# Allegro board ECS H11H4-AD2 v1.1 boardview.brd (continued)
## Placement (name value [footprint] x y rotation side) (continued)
Q25  mmbt3904-s  [SOT23_BCE_2]  156.18 65.66 270 top
Q26  mmbt3904-s  [SOT23_BCE_2]  167.49 65.02 0 top
Q27  sm2305psa-s  [SOT23_GDS_2]  153.9 59.18 0 top
Q28  sm2300nsac-trg-s  [SOT23_GDS_2]  135.86 58.8 180 top
Q29  sm2305psa-s  [SOT23_GDS_2]  135.88 54.78 0 top
Q30  sm2305psa-s  [SOT23_GDS_2]  146.76 47.12 0 top
Q31  mmbt3904-s  [SOT23_BCE_2]  139.29 46.99 180 top
Q32  mmbt3904-s  [SOT23_BCE_2]  97.3 34.55 270 top
Q33  mmbt3904-s  [SOT23_BCE_2]  97.31 30.94 270 top
Q34  pmbs3906-s-o  [SOT23_BCE_2]  36.8 29.03 0 top
Q35  mmbt3904-s  [SOT23_BCE_2]  194.79 28.83 0 top
Q36  pmbs3906-s-o  [SOT23_BCE_2]  36.78 25.17 0 top
Q37  mmbt3904-s  [SOT23_BCE_2]  10.36 10.41 180 top
Q38  pmbs3906-s  [SOT23_BCE_2]  26.39 10.29 270 top
Q39  mmbt3904-s  [SOT23_BCE_2]  5.28 10.03 270 top
Q40  mmbt3904-s  [SOT23_BCE_2]  5.2 5.23 270 top
Q44  pmbs3906-s  [SOT23_BCE_2]  158.98 220.47 90 top
QBH1  sm4377nskpc-trg-s  [Q_TDSON8-GDS-4]  116.05 59.18 0 top
QBL1  sm4364nakpc-trg-s  [Q_TDSON8-GDS-4]  116.05 51.56 0 top
QCGH1  sm4377nskpc-trg-s  [Q_TDSON8-GDS-4]  189.71 153.03 270 top
QCGH2  sm4377nskpc-trg-s  [Q_TDSON8-GDS-4]  189.71 135.51 270 top
QCGL1  sm4364nakpc-trg  [Q_TDSON8-GDS-4]  175.23 159.89 180 top
QCGL2  sm4364nakpc-trg  [Q_TDSON8-GDS-4]  183.36 159.89 180 top
QCGL3  sm4364nakpc-trg  [Q_TDSON8-GDS-4]  183.36 142.37 180 top
QCGL4  sm4364nakpc-trg  [Q_TDSON8-GDS-4]  175.23 142.37 180 top
QCH1  sm4377nskpc-trg-s  [Q_TDSON8-GDS-4]  124.82 201.17 0 top
QCH2  sm4377nskpc-trg-s  [Q_TDSON8-GDS-4]  140.56 201.17 0 top
QCH3  sm4377nskpc-trg-s  [Q_TDSON8-GDS-4]  189.71 170.94 270 top
QCL1  sm4364nakpc-trg  [Q_TDSON8-GDS-4]  117.32 186.18 270 top
QCL2  sm4364nakpc-trg  [Q_TDSON8-GDS-4]  117.32 194.31 270 top
QCL3  sm4364nakpc-trg  [Q_TDSON8-GDS-4]  135.15 186.18 270 top
QCL4  sm4364nakpc-trg  [Q_TDSON8-GDS-4]  135.1 194.31 270 top
QCL5  sm4364nakpc-trg  [Q_TDSON8-GDS-4]  183.24 177.8 180 top
QCL6  sm4364nakpc-trg  [Q_TDSON8-GDS-4]  175.11 177.8 180 top
QCSH1  sm4377nskpc-trg-s  [Q_TDSON8-GDS-4]  107.8 202.31 0 top
QCSL1  sm4364nakpc-trg  [Q_TDSON8-GDS-4]  103.86 195.45 270 top
QN1  nx7002ak-s  [SOT23_2MM_2]  114.86 229.18 270 top
QN2  nx7002ak-s  [SOT23_2MM_2]  114.86 225.76 270 top
QN3  apm2306ac-trg-s  [SOT23_GDS_2]  160.48 224.31 0 top
QN4  nx7002ak-s  [SOT23_2MM_2]  131.93 222.25 0 top
QN5  nx7002ak-s  [SOT23_2MM_2]  114.02 220.47 270 top
QN6  nx7002ak-s  [SOT23_2MM_2]  155.17 220.22 0 top
QN7  nx7002ak-s  [SOT23_2MM_2]  148.31 219.46 0 top
QN8  nx7002ak-s  [SOT23_2MM_2]  151.74 219.46 0 top
QN9  nx7002ak-s  [SOT23_2MM_2]  144.68 216.76 0 top
QN10  apm2306ac-trg-s  [SOT23_GDS_2]  122.66 215.01 0 top
QN11  nx7002ak-s-o  [SOT23_2MM_2]  9.12 147.32 90 top
QN12  nx7002ak-s  [SOT23_2MM_2]  57.76 130.05 180 top
QN13  nx7002ak-s  [SOT23_2MM_2]  182.65 127.84 0 top
QN14  nx3008nbk-s-o  [SOT23_GDS_2]  186.28 127.76 90 top
QN15  nx7002ak-s-o  [SOT23_2MM_2]  186.03 124.21 90 top
QN16  nx7002ak-s  [SOT23_2MM_2]  6.58 134.11 90 top
QN17  nx7002ak-s-o  [SOT23_2MM_2]  187.55 114.55 90 top
QN18  nx7002ak-s-o  [SOT23_2MM_2]  191.11 114.55 90 top
QN19  nx7002ak-s-o  [SOT23_2MM_2]  7.34 84.46 90 top
QN20  sm2203nsqg  [DFN6_PT065_SM2203NSQG]  161.01 73.66 180 top
QN21  nx7002ak-s  [SOT23_2MM_2]  139.55 60.2 90 top
QN22  nx7002ak-s  [SOT23_2MM_2]  139.55 56.77 90 top
QN23  nx7002ak-s  [SOT23_2MM_2]  132.31 46.99 180 top
QN24  nx7002ak-s  [SOT23_2MM_2]  135.74 46.99 180 top
QN25  nx7002ak-s  [SOT23_2MM_2]  104.11 44.96 180 top
QN26  nx7002ak-s-o  [SOT23_2MM_2]  164.57 30.23 270 top
QN27  nx7002ak-s  [SOT23_2MM_2]  129.9 27.18 0 top
QN28  nx7002ak-s  [SOT23_2MM_2]  134.47 27.18 0 top
QN29  nx7002ak-s  [SOT23_2MM_2]  141.33 27.18 0 top
QN30  nx7002ak-s  [SOT23_2MM_2]  144.75 27.18 0 top
QN31  nx7002ak-s  [SOT23_2MM_2]  155.42 27.18 0 top
QN32  nx7002ak-s  [SOT23_2MM_2]  158.85 27.18 0 top
QN33  nx7002ak-s  [SOT23_2MM_2]  43.15 19.69 180 top
QN34  nx7002ak-s  [SOT23_2MM_2]  46.58 19.69 180 top
QN35  nx7002ak-s  [SOT23_2MM_2]  43.15 16.26 180 top
QN36  nx7002ak-s  [SOT23_2MM_2]  46.58 16.26 180 top
QN37  nx7002ak-s  [SOT23_2MM_2]  51.13 15.93 180 top
QN39  nx7002ak-s-o  [SOT23_2MM_2]  194.81 119.3 90 top
QN40  nx7002ak-s-o  [SOT23_2MM_2]  189.84 50.93 0 top
QSW1  sm2313psac-trg-s-o  [SOT23_GDS_2]  55.09 188.85 270 top
QSW2  apm4500akc-trg-s  [SOP8_W150_PT50]  52.3 117.35 180 top
R1  1k-04-o  [R0402_2]  11.79 238.76 180 top
R2  1k-04  [R0402_2]  14.45 238.76 180 top
R3  1k-04  [R0402_2]  16.99 238.76 180 top
R4  1k-04  [R0402_2]  20.29 238.76 180 top
R5  1k-04  [R0402_2]  23.09 238.76 180 top
R6  1k-04-o  [R0402_2]  11.79 234.44 180 top
R7  1k-04  [R0402_2]  14.45 234.44 180 top
R8  1k-04  [R0402_2]  16.99 234.44 180 top
R9  1k-04  [R0402_2]  20.29 234.44 180 top
R10  1k-04  [R0402_2]  23.09 234.44 180 top
R11  0-08-o  [R0805_2]  163.22 233.32 270 top
R12  2.2k-04-o  [R0402_2]  188.37 233.05 270 top
R16  2.2k-04-o  [R0402_2]  189.46 233.05 270 top
R17  4.7k-04  [R0402_2]  190.6 233.05 90 top
R18  200-1-04-o  [R0402_2]  183.62 232.28 180 top
R19  4.7k-04  [R0402_2]  13.18 231.39 90 top
R21  4.7k-04  [R0402_2]  14.45 231.39 90 top
R22  0-04-o  [R0402_2]  170.46 230.84 270 top
R23  33-04-o  [R0402_2]  171.53 230.84 90 top
R24  0-04-o  [R0402_2]  166.88 230.81 270 top
R25  33-04-o  [R0402_2]  167.94 230.81 90 top
R26  75-04-o  [R0402_2]  180.82 230.2 90 top
R27  2.2k-04  [R0402_2]  126.29 229.62 0 top
R28  2.2k-04  [R0402_2]  112.5 230 270 top
R29  75-04-o  [R0402_2]  180.82 227.66 90 top
R30  20k-04  [R0402_2]  133.07 226.31 270 top
R31  39.2k-1-04  [R0402_2]  11.53 225.81 270 top
R32  20k-1-04  [R0402_2]  12.67 225.81 270 top
R33  2.2k-04  [R0402_2]  13.94 225.81 90 top
R34  2.2k-04  [R0402_2]  19.15 225.81 90 top
R35  2.2k-04  [R0402_2]  114.27 223.39 180 top
R37  100-1-04  [R0402_2]  166.85 225.68 0 top
R38  22k-04  [R0402_2]  40.36 225.4 270 top
R39  75-04  [R0402_2]  28.57 225.3 0 top
R40  75-04-o  [R0402_2]  180.82 225.22 90 top
R41  2.2k-04  [R0402_2]  126.29 225.04 0 top
R42  0-08-o  [R0805_2]  163.25 224.56 90 top
R43  22k-04  [R0402_2]  38.46 224.41 0 top
R44  1k-04  [R0402_2]  109.12 224.21 270 top
R45  3.74k-1-04  [R0402_2]  166.09 224.03 270 top
R46  1k-04  [R0402_2]  169.52 224.03 90 top
R47  100k-1-04  [R0402_2]  173.23 224.03 90 top
R48  100k-1-04  [R0402_2]  174.35 224.03 90 top
R49  75-04  [R0402_2]  28.57 223.27 0 top
R50  10k-04  [R0402_2]  158.14 223.37 90 top
R51  470-04  [R0402_2]  116.56 222.88 270 top
R56  470-04  [R0402_2]  117.7 222.88 270 top
R57  470-04  [R0402_2]  118.85 222.88 270 top
R58  470-04  [R0402_2]  119.99 222.88 270 top
R59  470-04  [R0402_2]  121.13 222.88 270 top
R60  470-04  [R0402_2]  122.28 222.88 270 top
R61  470-04  [R0402_2]  123.42 222.88 270 top
R62  470-04  [R0402_2]  124.56 222.88 270 top
R63  20k-04  [R0402_2]  154.91 222.5 0 top
R64  2.2k-04  [R0402_2]  148.63 222.38 270 top
R65  2.2k-04  [R0402_2]  149.71 222.38 270 top
R66  3.74k-1-04  [R0402_2]  164.95 221.87 270 top
R67  510-1-04  [R0402_2]  166.09 221.87 270 top
R68  2.2k-04  [R0402_2]  145.96 222.63 0 top
R69  2.2k-04  [R0402_2]  152.44 221.74 0 top
R70  11k-1-04  [R0402_2]  171.91 221.56 90 top
R71  2.2-1-04  [R0402_2]  173.2 221.23 90 top
R72  100k-1-04  [R0402_2]  174.65 221.23 90 top
R73  1.82k-1-04  [R0402_2]  175.72 221.23 90 top
R74  75-04  [R0402_2]  3.63 221.03 90 top
R77  75-04  [R0402_2]  28.57 220.45 180 top
R78  470-04  [R0402_2]  134.34 220.09 270 top
R79  470-04  [R0402_2]  135.48 220.09 270 top
R80  470-04  [R0402_2]  136.63 220.09 270 top
R81  470-04  [R0402_2]  137.77 220.09 270 top
R82  470-04  [R0402_2]  138.91 220.09 270 top
R83  470-04  [R0402_2]  140.06 220.09 270 top
R84  470-04  [R0402_2]  141.2 220.09 270 top
R85  470-04  [R0402_2]  142.34 220.09 270 top
R86  1m-04  [R0402_2]  131.93 219.96 0 top
R88  75-04  [R0402_2]  28.57 219.35 0 top
R89  220k-04  [R0402_2]  41.76 219.2 270 top
R90  200k-1-04-o  [R0402_2]  174.27 219.13 270 top
R91  1.82k-1-04  [R0402_2]  175.49 219.13 90 top
R92  24.3k-1-04  [R0402_2]  162.66 218.95 90 top
R93  100-1-04  [R0402_2]  167.23 218.95 90 top
R94  301-1-04  [R0402_2]  168.68 218.95 90 top
R95  2.61k-1-04  [R0402_2]  169.9 218.95 90 top
R96  200k-1-04-o  [R0402_2]  180.19 218.95 90 top
R97  2.2-1-04  [R0402_2]  181.33 218.95 270 top
R98  100k-1-04  [R0402_2]  182.47 218.95 90 top
R99  100k-1-04  [R0402_2]  184.76 218.95 270 top
R100  0-08  [R0805_2]  158.72 217.68 180 top
R101  75-04  [R0402_2]  28.57 218.26 0 top
R102  22k-04  [R0402_2]  59.69 217.93 180 top
R103  1m-04  [R0402_2]  155.17 217.93 0 top
R104  22k-04  [R0402_2]  51 217.91 180 top
R105  22k-04  [R0402_2]  53.54 217.91 0 top
R106  20k-1-04  [R0402_2]  11.53 217.83 0 top
R107  22k-04  [R0402_2]  44.93 217.81 0 top
R108  1k-04  [R0402_2]  28.57 217.17 0 top
R109  10k-04  [R0402_2]  41.76 217.04 270 top
R110  1k-04  [R0402_2]  164.87 216.87 270 top
R111  88.7k-1-04  [R0402_2]  163.8 216.87 90 top
R112  0-04-o  [R0402_2]  179.68 216.41 180 top
R113  100k-1-04  [R0402_2]  181.33 216.41 270 top
R114  1.82k-1-04  [R0402_2]  182.47 216.41 90 top
R115  1.82k-1-04  [R0402_2]  183.62 216.41 90 top
R116  100k-1-04  [R0402_2]  172.34 216.33 0 top
R117  4.99k-1-04  [R0402_2]  173.91 215.85 90 top
R118  short pad  [R0603-SHORT_1-NMNP]  45.19 215.39 270 top
R119  1k-04  [R0402_2]  28.57 215.14 0 top
R120  0-08-o  [R0805_2]  127.1 215.14 90 top
R121  11k-1-04  [R0402_2]  176.3 214.99 0 top
R122  40.2k-1-04  [R0402_2]  178.38 214.99 180 top
R123  1k-04  [R0402_2]  86 214.3 0 top
R124  0  [R0603_2]  81.23 214.12 270 top
R125  10k-04  [R0402_2]  120.24 214.12 90 top
R126  330  [R0603_2]  77.57 213.87 270 top
R128  200k-1-04-o  [R0402_2]  182.47 213.87 90 top
R130  75-04  [R0402_2]  3.61 213.77 270 top
R131  2.2-08  [R0805_2]  154.79 213.74 0 top
R132  330-o  [R0603_2]  65.02 213.66 90 top
R133  330-o  [R0603_2]  66.42 213.66 90 top
R134  12.1k-1-04  [R0402_2]  174.98 212.85 0 top
R135  2.87k-1-04  [R0402_2]  177.52 212.85 0 top
R136  22k-04  [R0402_2]  6.71 212.72 0 top
R137  75-04  [R0402_2]  28.42 212.72 180 top
R138  20k-1-04  [R0402_2]  24.23 212.34 270 top
R139  10k-1-04  [R0402_2]  25.37 212.34 270 top
R140  5.1k-1-04  [R0402_2]  26.52 212.34 270 top
R141  10-1-04  [R0402_2]  172.44 211.71 0 top
R142  100-1-04  [R0402_2]  174.98 211.71 0 top
R143  22k-04-o  [R0402_2]  177.52 211.71 0 top
R144  10k-04  [R0402_2]  41.88 211.46 270 top
R145  2.2-08  [R0805_2]  154.79 211.46 0 top
R146  100k-1-04  [R0402_2]  181.33 211.33 90 top
R147  2.2-1-04  [R0402_2]  182.47 211.33 270 top
R148  100k-1-04  [R0402_2]  183.62 211.33 90 top
R149  150  [R0603_2]  65 210.69 270 top
R150  150  [R0603_2]  66.4 210.69 270 top
R151  0-04-o  [R0402_2]  17.5 210.57 270 top
R152  33-04  [R0402_2]  20.04 210.57 90 top
R153  4.7k-04  [R0402_2]  102.87 217.02 270 top
R154  0-04  [R0402_2]  172.54 210.57 0 top
R155  0-04-o  [R0402_2]  174.98 210.57 0 top
R156  2k-1-04  [R0402_2]  178.54 210.57 180 top
R157  49.9-1-04  [R0402_2]  172.44 209.42 0 top
R158  45.3-1-04  [R0402_2]  174.98 209.42 0 top
R159  301-1-04-o  [R0402_2]  177.06 209.42 0 top
R160  1k-04  [R0402_2]  41.88 209.3 270 top
R161  short pad  [R0603-SHORT_1-NMNP]  24.61 209.04 270 top
R162  100k-1-04  [R0402_2]  181.33 208.79 270 top
R163  1.82k-1-04  [R0402_2]  182.47 208.79 90 top
R164  1.82k-1-04  [R0402_2]  183.62 208.79 90 top
R165  17.4k-1-04  [R0402_2]  169.9 208.28 0 top
R166  100k-1-04  [R0402_2]  177.06 208.28 0 top
R167  0-08  [R0805_2]  154.66 208.03 180 top
R168  0-04  [R0402_2]  22.2 207.9 270 top
R169  0-04  [R0402_2]  18.9 207.77 90 top
R170  2.2-08  [R0805_2]  158.34 207.65 180 top
R171  22k-04  [R0402_2]  11.96 207.59 270 top
R172  1k-04  [R0402_2]  41.88 207.14 90 top
R173  0-04-o  [R0402_2]  169.9 207.14 0 top
R174  23.2k-1-04  [R0402_2]  172.44 207.14 180 top
R175  9.53k-1-04  [R0402_2]  177.06 207.14 0 top
R176  4.7k-04  [R0402_2]  158.98 206.12 180 top
R177  4.7k-04  [R0402_2]  158.98 204.98 180 top
R178  267-1-04  [R0402_2]  167.67 204.98 90 top
R179  200k-1-04-o  [R0402_2]  170.54 204.98 270 top
R180  200k-1-04-o  [R0402_2]  174.35 204.98 90 top
R181  2.2-08  [R0805_2]  154.79 204.98 180 top
R182  1k-04  [R0402_2]  164.24 204.24 270 top
R183  2.49k-1-04  [R0402_2]  58.7 203.56 0 top
R184  26.1k-1-04-o  [R0402_2]  157.33 202.69 270 top
R185  100k-1-04  [R0402_2]  161.52 203.33 0 top
R186  1k-04  [R0402_2]  167.11 203.33 180 top
R187  100k-1-04  [R0402_2]  169.47 202.82 90 top
R188  100k-1-04  [R0402_2]  170.54 202.82 270 top
R189  2.2-1-04  [R0402_2]  173.2 202.82 270 top
R190  100k-1-04  [R0402_2]  174.35 202.82 90 top
R191  100k-1-04  [R0402_2]  175.74 202.82 270 top
R192  0-04  [R0402_2]  90.27 202.44 0 top
R193  56k-04  [R0402_2]  158.98 202.18 180 top
R194  200-04  [R0402_2]  161.52 202.18 180 top
R195  68.1-1-04-o  [R0402_2]  93.07 201.93 90 top
R196  4.99k-1-04  [R0402_2]  94.21 201.93 90 top
R197  10k-1-04  [R0402_2]  95.35 201.93 90 top
R198  64.9k-1-04  [R0402_2]  96.49 201.93 90 top
R199  10k-1-04  [R0402_2]  97.64 201.93 90 top
R200  0-04  [R0402_2]  98.7 201.93 90 top
R201  3.6k-04  [R0402_2]  163.17 201.68 90 top
R202  100-1-04  [R0402_2]  165.46 201.68 270 top
R203  0-04  [R0402_2]  90.27 201.3 180 top
R204  1k-04  [R0402_2]  158.98 201.04 0 top
R205  11k-1-04  [R0402_2]  167.11 201.04 0 top
R206  10k-04  [R0402_2]  46.71 200.91 180 top
R207  2.2-1-04  [R0402_2]  169.39 200.28 90 top
R208  1.82k-1-04  [R0402_2]  170.54 200.28 90 top
R209  1.82k-1-04  [R0402_2]  171.68 200.28 90 top
R210  2.61k-1-04  [R0402_2]  173.2 200.28 90 top
R211  1.82k-1-04  [R0402_2]  174.35 200.28 270 top
R212  1.82k-1-04  [R0402_2]  175.49 200.28 90 top
R213  10k-04  [R0402_2]  72.92 200.03 0 top
R214  100-1-04  [R0402_2]  161.52 199.9 180 top
R215  10-04  [R0402_2]  91.92 199.52 90 top
R216  470k-1-04  [R0402_2]  93.07 199.52 270 top
R217  2.2-08  [R0805_2]  102.97 199.52 0 top
R218  10k-1-04  [R0402_2]  109.07 197.99 0 top
R219  0-04  [R0402_2]  60.3 197.49 270 top
R220  0-08  [R0805_2]  145.39 197.1 180 top
R221  0-08  [R0805_2]  129.51 196.98 180 top
R222  10k-1-04  [R0402_2]  126.09 196.85 0 top
R223  10k-1-04  [R0402_2]  141.83 196.85 0 top
R224  1k-04  [R0402_2]  50.27 195.91 90 top
R225  3.3k-04  [R0402_2]  48.03 195.88 270 top
R226  15k-04  [R0402_2]  49.1 195.88 270 top
R227  0-08  [R0805_2]  110.46 195.71 90 top
R228  22k-04  [R0402_2]  3.89 194.89 270 top
R229  0-08  [R0805_2]  92.96 194.67 270 top
R230  2.2-08  [R0805_2]  97.13 194.44 270 top
R231  22k-04  [R0402_2]  6.83 193.93 180 top
R232  1k-04  [R0402_2]  50.12 193.13 270 top
R233  0-04-o  [R0402_2]  51.28 193.12 270 top
R234  0-06-short  [R0603-SHORT_2]  53.57 192.79 180 top
R235  1k-04-o  [R0402_2]  73.51 192.79 0 top
R236  short pad  [R0603-SHORT_1-NMNP]  4.67 192.74 0 top
R237  1k-04-o  [R0402_2]  73.51 191.64 0 top
R238  1k-04-o  [R0402_2]  73.51 190.5 0 top
R239  2.2-08  [R0805_2]  116.56 190.25 0 top
R240  2.2-08  [R0805_2]  134.21 190.25 0 top
R241  100k-04-o  [R0402_2]  52.55 189.99 90 top
R242  1k-04-o  [R0402_2]  73.51 189.36 180 top
R243  1k-04-o  [R0402_2]  73.51 188.21 180 top
R244  1k-04-o  [R0402_2]  70.97 187.07 180 top
R245  1k-04-o  [R0402_2]  73.51 187.07 180 top
R246  33-04  [R0402_2]  43.65 186.31 270 top
R247  0  [R0603_2]  54.58 186.31 0 top
R248  33-04  [R0402_2]  23.34 186.06 90 top
R249  1k-04-o  [R0402_2]  70.97 185.93 180 top
R250  1k-04-o  [R0402_2]  73.51 185.93 180 top
R251  1k-04-o  [R0402_2]  70.97 184.78 180 top
R252  1k-04-o  [R0402_2]  73.51 184.78 180 top
R253  1k-04  [R0402_2]  26.26 183.64 270 top
R254  0-04-o  [R0402_2]  31.72 183.64 270 top
R255  1k-04-o  [R0402_2]  70.97 183.64 180 top
R256  1k-04-o  [R0402_2]  73.51 183.64 180 top
R257  1k-04-o  [R0402_2]  70.97 182.5 180 top
R258  1k-04-o  [R0402_2]  73.51 182.5 180 top
R259  1k-04-o  [R0402_2]  70.97 181.36 180 top
R260  1k-04-o  [R0402_2]  73.51 181.36 180 top
R261  0-08  [R0805_2]  188.19 180.34 180 top
R262  0-04-o  [R0402_2]  70.97 180.21 180 top
R263  0-04-o  [R0402_2]  70.97 179.07 180 top
R264  2.2-08  [R0805_2]  179.17 178.69 270 top
R265  51-04-o  [R0402_2]  70.97 177.93 0 top
R266  51-04-o  [R0402_2]  73.51 177.93 180 top
R267  0-04  [R0402_2]  66.9 176.78 0 top
R268  1k-04-o  [R0402_2]  70.97 176.78 0 top
R269  0-04-o  [R0402_2]  73.51 176.78 180 top
R270  0-04-o  [R0402_2]  66.9 175.64 0 top
R271  0-04-o  [R0402_2]  73.51 175.64 180 top
R272  0-08  [R0805_2]  188.57 175.01 180 top
R273  20-04  [R0402_2]  66.9 174.5 180 top
R274  0-04  [R0402_2]  66.9 172.21 180 top
R275  0-04  [R0402_2]  73.51 171.07 0 top
R276  51-04-o  [R0402_2]  73.51 169.93 0 top
R277  10k-1-04  [R0402_2]  185.39 169.67 270 top
R278  0-08  [R0805_2]  186.92 166.24 90 top
R279  12.1k-1-04-o  [R0402_2]  4.93 163.83 180 top
R280  3.83k-1-04-o  [R0402_2]  4.17 161.8 270 top
R281  2.2-08  [R0805_2]  179.3 160.78 270 top
R282  2.8k-1-04  [R0402_2]  73.51 155.7 180 top
R283  6.04k-1-04  [R0402_2]  73.51 154.56 0 top
R284  20-1-04  [R0402_2]  73.51 153.42 180 top
R285  24.9-1-04  [R0402_2]  114.25 152.32 270 top
R286  24.9-1-04  [R0402_2]  115.32 152.32 90 top
R287  49.9-1-04  [R0402_2]  116.38 152.32 270 top
R288  560-04-o  [R0402_2]  117.45 152.32 270 top
R289  0-o  [R0603_2]  72.87 152.16 0 top
R290  10k-1-04  [R0402_2]  185.42 151.76 270 top
R291  100k-04-o  [R0402_2]  4.42 151.13 0 top
R292  0-04-o  [R0402_2]  4.42 149.99 0 top
R293  0-08  [R0805_2]  188.32 148.97 180 top
R294  10k-04-o  [R0402_2]  6.2 145.03 180 top
R295  1k-04-o  [R0402_2]  9.88 145.03 180 top
R296  0-08  [R0805_2]  189.59 144.91 180 top
R297  0-04  [R0402_2]  69.57 144.78 90 top
R298  2.2-08  [R0805_2]  179.3 143.26 270 top
R299  0-04  [R0402_2]  114.25 142.77 270 top
R300  0-04  [R0402_2]  73.1 140.11 180 top
R301  0-08  [R0805_2]  189.97 139.57 180 top
R302  1k-04  [R0402_2]  3.91 134.87 90 top
R303  10k-1-04  [R0402_2]  185.42 134.24 270 top
R304  0-08  [R0805_2]  187.05 131.44 180 top
R305  0-04  [R0402_2]  8.99 131.19 90 top
R306  4.7k-04  [R0402_2]  50.77 129.41 270 top
R307  4.7k-04  [R0402_2]  51.92 129.41 270 top
R308  4.7k-04  [R0402_2]  53.06 129.41 90 top
R309  1k-04-o  [R0402_2]  8.99 129.08 270 top
R310  4.7k-04  [R0402_2]  54.71 128.91 180 top
R311  0-04-o  [R0402_2]  180.44 128.65 270 top
R312  0-04  [R0402_2]  56.36 127.25 90 top
R313  240-12-o  [R1206]  191.87 127.18 180 top
R314  100-04-o  [R0402_2]  8.99 127 270 top
R315  1m-1-04-o  [R0402_2]  62.97 126.97 0 top
R316  10k-04  [R0402_2]  183.11 125.35 180 top
R317  4.7-1  [R0603_2]  58.8 125.15 180 top
R318  8.2k-04  [R0402_2]  56.36 125.09 90 top
R319  1k-04  [R0402_2]  9.02 124.89 90 top
R320  240-12-o  [R1206]  191.87 124.71 180 top
R321  0-04-o  [R0402_2]  183.11 124.21 180 top
R322  10k-04-o  [R0402_2]  188.29 123.47 270 top
R323  20k-04  [R0402_2]  66.22 123.19 0 top
R324  10k-1-04-o  [R0402_2]  67.87 123.19 270 top
R325  0-04  [R0402_2]  69.01 123.19 90 top
R326  100k-04-o  [R0402_2]  183.08 123.07 180 top
R327  100-04  [R0402_2]  56.74 122.81 0 top
R328  1k-04  [R0402_2]  9.02 122.58 270 top
R329  240-12-o  [R1206]  191.87 122.28 180 top
R330  100k-04-o  [R0402_2]  66.22 122.05 180 top
R331  0-04  [R0402_2]  56.74 121.67 180 top
R332  6.34k-1-04  [R0402_2]  58.9 121.67 0 top
R333  10k-04-o  [R0402_2]  184.23 121.01 90 top
R334  4.7k-04-o  [R0402_2]  185.34 121.01 270 top
R335  4.7k-04-o  [R0402_2]  186.44 121.01 90 top
R336  4.7k-04  [R0402_2]  188.57 121.01 270 top
R337  11k-1-04  [R0402_2]  56.74 120.6 0 top
R338  499-1-04-o  [R0402_2]  56.74 119.53 180 top
R339  100k-04-o  [R0402_2]  58.9 119.38 0 top
R340  1k-04  [R0402_2]  9.02 118.92 270 top
R341  499k-1-04-o  [R0402_2]  58.9 118.24 0 top
R342  0-04-o  [R0402_2]  194.94 116.59 90 top
R343  7.87k-04  [R0402_2]  161.52 219.46 90 top
R344  0-04  [R0402_2]  8.05 114.76 90 top
R345  1k-04-o  [R0402_2]  183.62 114.43 90 top
R346  0-04-o  [R0402_2]  184.76 114.43 270 top
R347  0-04-o  [R0402_2]  194.79 113.92 90 top
R348  10k-04-o  [R0402_2]  188.34 112.34 0 top
R349  4.7k-04  [R0402_2]  183.68 112 0 top
R350  100-04  [R0402_2]  186.13 112 0 top
R351  27k-04  [R0402_2]  186.16 110.87 180 top
R352  22k-04  [R0402_2]  183.64 110.86 0 top
R353  0-04-o  [R0402_2]  3.91 110.46 270 top
R354  0-04  [R0402_2]  31.72 110.24 270 top
R355  0-04  [R0402_2]  32.87 110.24 90 top
R356  1k-04-o  [R0402_2]  8.05 109.14 270 top
R357  10k-04  [R0402_2]  32.87 108.08 90 top
R358  4.7k-04  [R0402_2]  188.95 107.57 270 top
R359  4.7k-04  [R0402_2]  8.38 107.09 270 top
R360  1k-04-o  [R0402_2]  8.38 104.93 270 top
R361  1k-04  [R0402_2]  6.86 103.61 0 top
R362  0  [R0603_2]  55.28 101.22 270 top
R363  0-04  [R0402_2]  49.25 100.46 90 top
R364  0-04  [R0402_2]  51.54 100.46 90 top
R365  0-04  [R0402_2]  54.02 100.44 90 top
R366  3.3k-04-o  [R0402_2]  28.3 98.17 90 top
R367  0-04  [R0402_2]  29.44 98.17 270 top
R368  0-04  [R0402_2]  30.71 98.17 90 top
R369  10k-04-o  [R0402_2]  31.85 98.17 90 top
R370  10k-04  [R0402_2]  32.99 98.17 90 top
R371  0-04  [R0402_2]  34.14 98.17 90 top
R372  1k-1-04  [R0402_2]  107.16 89.66 0 top
R373  0-04  [R0402_2]  107.16 90.81 0 top
R374  1k-1-04  [R0402_2]  105.58 90.3 270 top
R375  1k-1-04  [R0402_2]  163.93 90.3 90 top
R376  1k-1-04  [R0402_2]  165.2 90.3 270 top
R377  0-04  [R0402_2]  167.49 90.3 270 top
R378  0  [R0603_2]  57.47 90.27 0 top
R379  0-04  [R0402_2]  55.51 90.25 90 top
R380  0-04  [R0402_2]  59.59 90.25 90 top
R381  0-04  [R0402_2]  60.73 90.25 270 top
R382  2-1-04  [R0402_2]  180.09 90.22 270 top
R383  24.9-1-04  [R0402_2]  182.88 90.22 90 top
R384  0  [R0603_2]  6.96 86.87 180 top
R385  1k-04-o  [R0402_2]  5.08 83.77 90 top
R386  2-1-04  [R0402_2]  109.7 80.65 180 top
R387  24.9-1-04  [R0402_2]  113.51 79.63 270 top
R388  1k-1-04  [R0402_2]  170.36 79.83 270 top
R389  1k-1-04  [R0402_2]  171.5 79.83 90 top
R390  0-04  [R0402_2]  173.71 79.76 90 top
R391  0-12  [R1206]  195.71 125.86 270 top
R392  2-1-04  [R0402_2]  179.76 79.83 270 top
R393  24.9-1-04  [R0402_2]  180.06 77.85 180 top
R394  1k-04  [R0402_2]  4.67 78.99 90 top
R395  1-1-08  [R0805_2]  140.06 78.61 180 top
R396  2.2-1  [R0603_2]  149.2 78.23 0 top
R397  8.2k-04  [R0402_2]  144.12 77.85 90 top
R398  100k-04  [R0402_2]  149.2 76.96 180 top
R399  510k-1-04  [R0402_2]  149.2 75.82 0 top
R400  0-04  [R0402_2]  151.74 74.42 180 top
R401  0-04  [R0402_2]  151.74 73.28 180 top
R402  8.2k-04-o  [R0402_2]  149.07 72.14 0 top
R403  8.2k-04  [R0402_2]  151.74 70.99 0 top
R404  10.2k-1-04  [R0402_2]  153.9 70.99 180 top
R405  0  [R0603_2]  75.79 70.61 90 top
R406  10k-04  [R0402_2]  84.94 70.36 0 top
R407  10k-04-o  [R0402_2]  87.78 70.36 0 top
R408  100-1-04  [R0402_2]  57.45 70.99 90 top
R409  2.7k-1-04  [R0402_2]  48.59 70.26 0 top
R410  0-04  [R0402_2]  151.74 69.85 0 top
R411  4.7k-04  [R0402_2]  157.07 69.34 0 top
R412  10k-04  [R0402_2]  84.94 69.22 180 top
R413  10k-04  [R0402_2]  87.78 69.22 0 top
R414  10k-04-o  [R0402_2]  189.33 53.34 180 top
R415  4.7k-04  [R0402_2]  163.8 68.96 90 top
R416  20k-1-04  [R0402_2]  188.19 68.33 0 top
R417  10k-04  [R0402_2]  84.94 67.69 180 top
R418  10k-04  [R0402_2]  87.78 67.69 0 top
R419  2.2-08  [R0805_2]  143.1 67.18 270 top
R420  0-08  [R0805_2]  180.57 67.06 0 top
R421  10k-04-o  [R0402_2]  84.94 66.55 180 top
R422  10k-04  [R0402_2]  87.78 66.55 180 top
R423  4.7k-04  [R0402_2]  158.72 66.42 90 top
R424  4.7k-04  [R0402_2]  163.8 66.42 270 top
R425  4.7k-04-o  [R0402_2]  164.95 66.42 270 top
R426  0-04  [R0402_2]  33.15 181.25 270 top
R427  4.7k-04  [R0402_2]  188.19 65.79 0 top
R428  0-04  [R0402_2]  144.63 65.66 270 top
R429  10k-04-o  [R0402_2]  84.94 65.41 180 top
R430  1k-04  [R0402_2]  87.78 65.41 0 top
R431  45.3k-1-04  [R0402_2]  191.11 64.9 270 top
R432  0-04  [R0402_2]  11.4 179.7 270 top
R433  1.5k-1-04  [R0402_2]  192.25 64.9 90 top
R434  1k-04  [R0402_2]  193.4 64.9 270 top
R435  10k-04  [R0402_2]  84.94 64.26 180 top
R436  10k-04-o  [R0402_2]  87.78 64.26 0 top
R437  0-04  [R0402_2]  14.45 59.44 180 top
R438  10k-04-o  [R0402_2]  158.85 63.63 90 top
R439  4.7k-04  [R0402_2]  161.52 63.63 90 top
R440  4.7k-04-o  [R0402_2]  162.66 63.63 90 top
R441  4.7k-04  [R0402_2]  163.8 63.63 90 top
R442  10k-04-o  [R0402_2]  84.94 63.12 180 top
R443  10k-04-o  [R0402_2]  87.78 63.12 180 top
R444  10k-04  [R0402_2]  84.94 61.98 0 top
R445  10k-04  [R0402_2]  87.78 61.98 0 top
R446  0  [R0603_2]  41.05 61.54 180 top
R447  10k-04  [R0402_2]  134.59 61.34 0 top
R448  1k-04-o  [R0402_2]  84.81 60.33 0 top
R449  10k-04  [R0402_2]  87.73 60.33 0 top
R450  0-04  [R0402_2]  44.04 60.2 180 top
R451  3.3k-04  [R0402_2]  84.81 59.18 0 top
R452  10k-04  [R0402_2]  87.73 59.18 0 top
R453  0-04  [R0402_2]  44.04 59.08 180 top
R454  10k-04  [R0402_2]  84.81 58.04 0 top
R455  10k-04-o  [R0402_2]  87.73 58.04 0 top
R456  4.7k-04  [R0402_2]  142.34 57.91 0 top
R457  0-08  [R0805_2]  124.43 57.78 90 top
R458  8.2k-04  [R0402_2]  84.81 56.9 0 top
R459  10k-04  [R0402_2]  87.73 56.9 0 top
R460  10k-04  [R0402_2]  13.82 57.28 90 top
R461  10k-04  [R0402_2]  80.62 56.26 0 top
R462  300k-04  [R0402_2]  153.9 56.13 270 top
R463  10k-04-o  [R0402_2]  84.81 55.75 180 top
R464  10k-04-o  [R0402_2]  87.73 55.75 0 top
R465  1k-04  [R0402_2]  33.88 55.65 0 top
R466  1k-04  [R0402_2]  36.68 55.65 0 top
R467  113-1-04  [R0402_2]  39.9 55.47 180 top
R468  12.1k-1-04  [R0402_2]  158.98 55.63 180 top
R473  10k-04  [R0402_2]  119.61 55.37 270 top
R474  0-08  [R0805_2]  121.13 55.37 90 top
R475  3.83k-1-04  [R0402_2]  157.07 54.99 90 top
R476  470k-1-04  [R0402_2]  128.5 54.74 0 top
R477  470-04-o  [R0402_2]  174.47 54.74 90 top
R478  10k-04  [R0402_2]  80.62 54.61 0 top
R479  10k-04-o  [R0402_2]  84.81 54.61 180 top
R480  10k-04  [R0402_2]  87.73 54.61 0 top
R481  0-04-o  [R0402_2]  14.96 57.28 90 top
R482  11k-1-04-o  [R0402_2]  177.9 54.48 270 top
R483  36k-1-04-o  [R0402_2]  179.04 54.48 90 top
R484  1k-04  [R0402_2]  4.17 53.85 180 top
R485  10-04  [R0402_2]  133.27 54.23 90 top
R486  30-04  [R0402_2]  33.88 54.13 180 top
R487  1k-04  [R0402_2]  36.68 54.13 0 top
R488  620-1-04  [R0402_2]  39.22 54.13 0 top
R489  10k-04  [R0402_2]  139.42 53.85 90 top
R490  680k-1-04  [R0402_2]  140.56 53.85 90 top
R491  4.7k-04  [R0402_2]  141.71 53.85 270 top
R492  68.1-1-04-o  [R0402_2]  128.5 53.59 0 top
R493  4.42k-1-04  [R0402_2]  130.58 53.59 0 top
R494  10k-04-o  [R0402_2]  80.62 53.47 0 top
R495  10k-04  [R0402_2]  84.81 53.47 0 top
R496  10k-04  [R0402_2]  87.73 53.47 180 top
R497  10k-04  [R0402_2]  192.91 53.42 90 top
R498  33-04  [R0402_2]  33.88 52.71 180 top
R499  1k-04  [R0402_2]  36.68 52.71 180 top
R500  10.5k-1-04  [R0402_2]  130.58 52.5 180 top
R501  4.7k-04-o  [R0402_2]  174.47 52.45 90 top
R502  10k-04-o  [R0402_2]  80.62 52.32 0 top
R503  10k-04  [R0402_2]  84.81 52.32 0 top
R504  10k-04  [R0402_2]  87.73 52.32 180 top
R505  4.7k-04  [R0402_2]  144.5 51.82 270 top
R506  22k-04  [R0402_2]  179.3 51.82 270 top
R507  22-04  [R0402_2]  39.22 51.31 180 top
R508  0-04  [R0402_2]  36.68 51.21 180 top
R509  10k-04  [R0402_2]  84.81 51.18 180 top
R510  10k-04  [R0402_2]  87.73 51.18 180 top
R511  10k-04  [R0402_2]  80.62 50.67 0 top
R512  100k-04  [R0402_2]  124.87 50.55 90 top
R513  82k-1-04  [R0402_2]  127.1 50.55 90 top
R514  2.2-08  [R0805_2]  122.28 50.16 180 top
R515  10k-04-o  [R0402_2]  84.81 50.04 0 top
R516  10k-04-o  [R0402_2]  87.73 50.04 0 top
R517  4.7k-04  [R0402_2]  133.45 50.04 270 top
R518  10k-04-o  [R0402_2]  134.59 50.04 90 top
R519  10k-04  [R0402_2]  135.74 50.04 90 top
R520  0-04  [R0402_2]  136.88 50.04 270 top
R521  4.7k-04  [R0402_2]  138.15 50.04 270 top
R522  8.2k-04  [R0402_2]  140.44 50.04 90 top
R523  10k-04-o  [R0402_2]  141.58 50.04 90 top
R524  33-04  [R0402_2]  40.45 49.96 0 top
R525  4.7k-04  [R0402_2]  178.16 49.66 270 top
R526  10k-04-o  [R0402_2]  156.06 202.69 270 top
R527  27k-04  [R0402_2]  179.3 49.66 90 top
R528  51-04  [R0402_2]  36.68 49.1 0 top
R529  33-04  [R0402_2]  41.68 48.9 0 top
R530  10k-04  [R0402_2]  84.81 48.9 0 top
R531  10k-04  [R0402_2]  87.73 48.9 180 top
R532  51-04-o  [R0402_2]  39.27 48.13 180 top
R533  1-1-08  [R0805_2]  108.81 47.88 180 top
R534  10k-04  [R0402_2]  84.81 47.75 0 top
R535  10k-04  [R0402_2]  87.73 47.75 0 top
R536  0-04  [R0402_2]  192.63 47.62 270 top
R537  15k-04-o  [R0402_2]  178.16 47.37 270 top
R538  100-04  [R0402_2]  179.31 47.31 90 top
R539  33-04  [R0402_2]  93.04 47.09 270 top
R540  33-04  [R0402_2]  94.13 47.09 270 top
R541  51-04  [R0402_2]  39.27 47.07 0 top
R542  0-08  [R0805_2]  118.85 46.84 180 top
R543  10k-04  [R0402_2]  87.73 46.69 0 top
R544  0-04-o  [R0402_2]  97.66 46.48 270 top
R545  10k-04  [R0402_2]  84.81 46.35 0 top
R546  4.7k-04  [R0402_2]  178.66 45.72 180 top
R549  10k-04  [R0402_2]  87.73 45.62 0 top
R550  10k-04-o  [R0402_2]  84.81 45.29 0 top
R552  33-04-o  [R0402_2]  93.04 44.6 90 top
R553  33-04-o  [R0402_2]  94.13 44.6 90 top
R554  300k-04  [R0402_2]  144.4 44.58 180 top
R555  2.2k-04  [R0402_2]  137.85 44.45 180 top
R556  0  [R0603_2]  34.57 44.2 90 top
R557  2.2k-04  [R0402_2]  107.54 44.2 90 top
R558  2.2k-04  [R0402_2]  108.69 44.2 90 top
R559  2.2k-04  [R0402_2]  109.83 44.2 90 top
R560  10k-1-04  [R0402_2]  116.18 43.81 270 top
R561  10k-1-04  [R0402_2]  117.32 43.81 270 top
R562  10k-1-04  [R0402_2]  118.47 43.81 270 top
R563  2k-1-04  [R0402_2]  119.61 43.81 90 top
R564  17.4k-1-04  [R0402_2]  120.88 43.81 270 top
R565  10k-04  [R0402_2]  87.78 42.82 0 top
R566  51-04  [R0402_2]  33.38 42.57 270 top
R567  8.2k-04  [R0402_2]  85.24 42.24 0 top
R568  10k-1-04  [R0402_2]  121.28 42.24 0 top
R569  0-04-o  [R0402_2]  36.93 42.04 180 top
R570  0-04  [R0402_2]  80.21 41.96 180 top
R571  120  [R0603_2]  102.97 41.78 90 top
R572  10k-04-o  [R0402_2]  104.19 41.4 90 top
R573  1k-04  [R0402_2]  105.26 41.4 90 top
R574  680-04-o  [R0402_2]  106.4 41.4 90 top
R575  680-04-o  [R0402_2]  107.54 41.4 90 top
R576  680-04-o  [R0402_2]  108.69 41.4 90 top
R577  2k-04-o  [R0402_2]  109.75 41.4 90 top
R578  0-04  [R0402_2]  110.82 41.4 90 top
R579  10k-04  [R0402_2]  85.24 41.17 0 top
R580  1k-04  [R0402_2]  87.78 41.17 0 top
R581  10k-1-04  [R0402_2]  122.91 41.02 0 top
R582  5.1k-1-04  [R0402_2]  125.45 41.02 180 top
R583  0-04-o  [R0402_2]  36.93 40.89 180 top
R584  0-04  [R0402_2]  80.24 40.89 180 top
R585  20k-04  [R0402_2]  85.24 40.11 0 top
R586  10k-1-04  [R0402_2]  122.91 39.88 0 top
R587  ntc-10k-1-04  [R0402_2]  125.45 39.88 180 top
R588  4.7k-04-o  [R0402_2]  82.75 39.83 180 top
R589  100k-04-o  [R0402_2]  36.93 39.75 180 top
R590  20k-04-o  [R0402_2]  87.73 39.04 180 top
R591  499-1-04  [R0402_2]  80.72 38.79 0 top
R592  4.7k-04-o  [R0402_2]  96.37 38.74 90 top
R593  2.2k-04-o  [R0402_2]  36.93 38.61 180 top
R594  0-o  [R0603_2]  100.94 38.23 90 top
R595  1k-04  [R0402_2]  84.81 37.97 180 top
R596  4.7k-04  [R0402_2]  87.73 37.97 180 top
R597  1.21k-1-04  [R0402_2]  65.51 37.59 0 top
R598  4.7k-04-o  [R0402_2]  67.92 37.59 180 top
R599  0  [R0603_2]  80.75 37.59 180 top
R600  2.2k-04-o  [R0402_2]  36.93 37.54 180 top
R601  0  [R0603_2]  45.95 37.47 0 top
R602  15-04  [R0402_2]  69.49 37.11 270 top
R603  100k-04  [R0402_2]  36.93 36.47 180 top
R604  20k-1-04  [R0402_2]  52.3 36.45 90 top
R605  1m-04  [R0402_2]  53.37 36.45 90 top
R606  10k-04  [R0402_2]  54.58 36.45 270 top
R607  10k-04  [R0402_2]  61.44 36.45 90 top
R608  10k-04  [R0402_2]  62.59 36.45 90 top
R609  0-04  [R0402_2]  63.73 36.45 270 top
R610  1k-04-o  [R0402_2]  65.51 36.45 0 top
R611  20k-04  [R0402_2]  67.92 36.45 180 top
R612  10k-04  [R0402_2]  71.73 36.45 90 top
R613  10k-04-o  [R0402_2]  72.87 36.45 270 top
R614  4.7k-04-o  [R0402_2]  74.02 36.45 270 top
R615  short pad  [R0603-SHORT_1-NMNP]  55.78 36.25 270 top
R616  4.7k-04  [R0402_2]  101.7 35.69 0 top
R617  0-short-04  [SHORT2-NMNP]  123.04 35.36 180 top
R618  0-04-short  [R0402-SHORT_2]  47.98 35.31 180 top
R619  15-04-o  [R0402_2]  65.51 35.31 0 top
R620  15-04  [R0402_2]  67.92 35.31 180 top
R621  0-04  [R0402_2]  101.7 34.42 0 top
R622  10k-04  [R0402_2]  122.68 34.14 0 top
R623  4.7k-04  [R0402_2]  53.44 33.78 270 top
R624  1k-04  [R0402_2]  54.58 33.78 270 top
R625  10k-04  [R0402_2]  60.38 33.78 270 top
R626  10k-04  [R0402_2]  61.44 33.78 270 top
R627  10k-04  [R0402_2]  62.59 33.78 270 top
R628  20k-04-o  [R0402_2]  63.73 33.78 270 top
R629  10k-04  [R0402_2]  71.73 33.78 270 top
R630  20k-04-o  [R0402_2]  74.14 33.78 270 top
R631  4.7k-04  [R0402_2]  75.54 33.78 90 top
R632  10k-04  [R0402_2]  78.08 33.78 90 top
R633  20k-04-o  [R0402_2]  79.22 33.78 270 top
R634  499-1-04  [R0402_2]  80.37 33.78 270 top
R635  10k-04  [R0402_2]  81.51 33.78 270 top
R636  10k-04  [R0402_2]  119.99 33.4 0 top
R637  1k-04  [R0402_2]  101.7 33.27 0 top
R638  2.2k-04  [R0402_2]  122.68 32.99 0 top
R639  510-04  [R0402_2]  94.21 32.72 0 top
R640  10k-04  [R0402_2]  119.99 32.33 0 top
R641  10m-04  [R0402_2]  48.49 32.26 270 top
R642  2k-04  [R0402_2]  101.7 32.21 0 top
R643  0-04-o  [R0402_2]  104.88 32.21 0 top
R644  0-04  [R0402_2]  94.21 31.62 0 top
R645  0-04  [R0402_2]  50.42 31.27 90 top
R646  10k-04  [R0402_2]  119.99 31.27 0 top
R647  10k-04  [R0402_2]  52.3 31.24 270 top
R648  0-04-o  [R0402_2]  53.44 31.24 270 top
R649  10k-o  [R0603_2]  144.63 31.24 180 top
R650  0-04  [R0402_2]  101.7 31.14 180 top
R651  0  [R0603_2]  68.81 31.12 90 top
R652  10k-04  [R0402_2]  71.73 31.12 90 top
R653  10k-04  [R0402_2]  74.14 31.12 90 top
R654  10k-04  [R0402_2]  75.54 31.12 270 top
R655  10k-04  [R0402_2]  76.94 31.12 90 top
R656  10k-04  [R0402_2]  78.08 31.12 270 top
R657  4.7k-04-o  [R0402_2]  79.22 31.12 270 top
R658  8.2k-04  [R0402_2]  60.17 30.99 270 top
R659  4.7k-04-o  [R0402_2]  61.32 30.99 270 top
R660  4.7k-04-o  [R0402_2]  62.46 30.99 90 top
R661  1k-04  [R0402_2]  63.6 30.99 90 top
R662  56-1-04  [R0402_2]  59.11 30.96 270 top
R663  5.6k-1-04  [R0402_2]  92.05 30.48 0 top
R664  1.13k-1-04  [R0402_2]  94.21 30.48 0 top
R665  10k-04  [R0402_2]  119.99 30.2 0 top
R666  8.2k-04  [R0402_2]  130.66 29.97 90 top
R667  2.4k-1-04  [R0402_2]  132.18 29.97 270 top
R668  100-2512-2w-o  [R2512_1]  170.66 29.84 180 top
R669  100k-04  [R0402_2]  141.96 29.46 180 top
R670  10k-04  [R0402_2]  155.42 29.46 180 top
R671  10k-04  [R0402_2]  53.47 29.13 270 top
R672  100k-04  [R0402_2]  48.06 28.58 270 top
R673  1k-04  [R0402_2]  8.1 28.32 90 top
R674  10k-04  [R0402_2]  68.88 28.32 90 top
R675  10k-04  [R0402_2]  69.95 28.32 90 top
R676  10k-04  [R0402_2]  71.73 28.32 270 top
R677  10k-04  [R0402_2]  72.87 28.32 90 top
R678  4.7k-04-o  [R0402_2]  74.14 28.32 270 top
R679  20k-04-o  [R0402_2]  75.54 28.32 270 top
R680  1k-04-o  [R0402_2]  76.68 28.32 270 top
R681  0-04  [R0402_2]  101.7 28.19 0 top
R682  10k-04  [R0402_2]  50.9 28.07 270 top
R683  10k-04  [R0402_2]  51.97 28.07 90 top
R684  1k-04  [R0402_2]  119.99 27.97 180 top
R685  10k-04-o  [R0402_2]  43.79 27.94 180 top
R686  0-04  [R0402_2]  147.04 27.94 270 top
R687  0-04-o  [R0402_2]  148.18 27.94 270 top
R688  4.7k-04-o  [R0402_2]  153.14 27.94 270 top
R689  0-04  [R0402_2]  161.14 27.94 270 top
R690  0-04-o  [R0402_2]  162.28 27.94 270 top
R691  100k-04  [R0402_2]  132.18 27.81 90 top
R692  10k-04  [R0402_2]  136.75 27.81 270 top
R693  20k-1-04  [R0402_2]  137.9 27.81 270 top
R694  4.7k-04  [R0402_2]  122.78 26.87 180 top
R695  10k-04  [R0402_2]  61.77 26.75 270 top
R696  10k-04-o  [R0402_2]  104.88 26.67 0 top
R697  10k-04  [R0402_2]  116.99 26.67 270 top
R698  10k-04  [R0402_2]  118.14 26.67 270 top
R699  2.2k-04-o  [R0402_2]  107.9 26.37 270 top
R700  680-04  [R0402_2]  108.97 26.37 270 top
R701  10k-04  [R0402_2]  111.18 26.37 270 top
R702  43-04  [R0402_2]  113.31 26.37 270 top
R703  100-04  [R0402_2]  114.38 26.37 90 top
R704  4.99k-1-04  [R0402_2]  137.39 26.16 180 top
R705  1k-04  [R0402_2]  193.27 26.16 180 top
R706  0-04-o  [R0402_2]  86.59 25.91 270 top
R707  0-04-o  [R0402_2]  87.73 25.91 270 top
R708  0-04-o  [R0402_2]  90.27 25.91 90 top
R709  499-1-04-o  [R0402_2]  92.68 25.91 90 top
R710  4.7k-04  [R0402_2]  122.78 25.81 0 top
R711  100k-04  [R0402_2]  43.66 25.53 270 top
R712  100k-04  [R0402_2]  45.82 25.65 0 top
R713  249-1-04  [R0402_2]  47.47 25.53 90 top
R714  249-1-04  [R0402_2]  48.49 25.53 90 top
R715  0-04-o  [R0402_2]  70.84 25.4 90 top
R716  8.2k-04-o  [R0402_2]  71.98 25.4 90 top
R717  0-04-o  [R0402_2]  73.13 25.4 270 top
R718  4.7k-04-o  [R0402_2]  74.27 25.4 90 top
R719  0-04-o  [R0402_2]  75.41 25.4 90 top
R720  1k-04-o  [R0402_2]  191.11 25.02 180 top
R721  22-04-o  [R0402_2]  51.28 23.39 270 top
R722  56-1-04  [R0402_2]  52.43 23.39 270 top
R723  0-04  [R0402_2]  47.73 22.99 90 top
R724  0-04-o  [R0402_2]  48.87 22.99 270 top
R725  0-04  [R0402_2]  50.01 22.99 90 top
R726  1k-04  [R0402_2]  44.96 23.24 180 top
R727  1k-04  [R0402_2]  43.41 22.78 90 top
R728  1k-04  [R0402_2]  42.01 22.73 90 top
R729  1k-04  [R0402_2]  46.51 22.94 90 top
R730  51-04-o  [R0402_2]  32.16 21.59 90 top
R731  82-04-o  [R0402_2]  34.82 21.56 90 top
R732  1k-04-o  [R0402_2]  36.25 21.59 90 top
R733  1k-04-o  [R0402_2]  33.68 21.56 90 top
R734  10k-04  [R0402_2]  96.34 21.31 180 top
R735  0-04  [R0402_2]  96.34 20.24 0 top
R736  1k-04  [R0402_2]  48.87 16.61 270 top
R737  10k-04-o  [R0402_2]  76.94 16.13 180 top
R738  0-04  [R0402_2]  76.94 14.99 0 top
R739  0-04  [R0402_2]  81.51 14.99 0 top
R740  short pad  [R0603-SHORT_1-NMNP]  71.22 14.73 90 top
R741  10k-04  [R0402_2]  47.22 13.97 180 top
R742  470-1-04  [R0402_2]  81.51 13.84 0 top
R743  1k-04  [R0402_2]  50.5 13.69 180 top
R744  10k-04-o  [R0402_2]  10.13 13.46 90 top
R745  10k-04  [R0402_2]  11.25 13.46 90 top
R746  0-04-o  [R0402_2]  92.05 13.08 90 top
R747  0-04-o  [R0402_2]  93.19 13.08 270 top
R748  10k-04  [R0402_2]  70.74 12.47 180 top
R749  10k-04  [R0402_2]  17.88 12.45 270 top
R750  1k-04  [R0402_2]  4.27 12.4 180 top
R751  2k-04  [R0402_2]  6.43 12.4 180 top
R752  0-04-o  [R0402_2]  96.6 12.01 180 top
R753  0-04-o  [R0402_2]  96.6 10.87 180 top
R754  150  [R0603_2]  7.9 10.57 90 top
R755  56  [R0603_2]  22.68 9.86 270 top
R756  33-04  [R0402_2]  16.21 9.53 270 top
R757  0-04  [R0402_2]  23.9 9.5 90 top
R758  1k-04-o  [R0402_2]  56.64 8.33 0 top
R759  10k-04  [R0402_2]  56.64 7.26 0 top
R760  82  [R0603_2]  7.9 7.63 270 top
R761  1k-04  [R0402_2]  4.11 7.62 0 top
R762  2k-04  [R0402_2]  6.2 7.62 180 top
R763  0-04  [R0402_2]  70.71 7.11 180 top
R764  33  [R0603_2]  7.87 4.57 90 top
RJ1  0-04(1-2)  [RJ3_0402]  20.17 207.14 270 top
RJ2  0-08(2-3)  [RJ3_0805]  54.33 184.02 180 top
RJ3  0-04(2-3)  [RJ3_0402]  8.05 111.81 270 top
RJ4  0-04(2-3)  [RJ3_0402]  12.55 57.78 270 top
RJ5  8.2k-04(2-3)  [RJ3_0402]  76.94 37.34 0 top
RJ6  8.2k-04(2-3)  [RJ3_0402]  76.94 35.81 0 top
RJ7  8.2k-04(2-3)  [RJ3_0402]  72.87 32.89 270 top
RN1  0-8p4r  [8P4R]  118.47 225.73 0 top
RN2  0-8p4r  [8P4R]  122.71 225.73 0 top
RN3  0-8p4r  [8P4R]  136.07 223.32 0 top
RN4  0-8p4r  [8P4R]  140.51 223.32 0 top
RN5  0-8p4r  [8P4R]  99.24 220.37 0 top
RN6  0-8p4r  [8P4R]  94.97 220.34 0 top
RN7  0-8p4r  [8P4R]  90.86 218.57 0 top
RN9  0-8p4r  [8P4R]  16.23 40.08 90 top
RN10  0-8p4r  [8P4R]  16.23 36.07 90 top
RN11  0-8p4r  [8P4R]  17.25 31.57 90 top
RN12  150-8p4r-04  [8P4R-0402]  191.49 29.46 90 top
RN13  0-8p4r  [8P4R]  15.6 17.65 90 top
RT1  ntc-100k-1-04  [R0402_2]  120.62 200.41 90 top
RT2  ntc-10k-1-04  [R0402_2]  122.4 182.63 180 top
RT3  ntc-100k-1-04  [R0402_2]  191.62 148.59 270 top
RT4  ntc-10k-1-04  [R0402_2]  171.25 147.17 270 top
SATA1  sata3-7p2r-r  [SATA3_7P-HI-TOP]  107.7 69.49 270 top
SATA2  sata3-7p2r-r  [SATA3_7P-HI-TOP]  98.65 69.34 90 top
SC1  .1u-16vy5-04-x-o  [C0402_2]  172.42 233.55 180 bottom
SC2  100p-04-x-o  [C0402_2]  169.77 233.12 90 bottom
SC3  .1u-16vy5-04-x-o  [C0402_2]  177.04 232.66 270 bottom
SC4  100p-04-x-o  [C0402_2]  169.77 231.04 270 bottom
SC5  .1u-16vy5-04-x-o  [C0402_2]  129.11 227.79 90 bottom
SC6  .1u-16vx7-04-x-o  [C0402_2]  183.64 227.61 0 bottom
SC7  .1u-16vx7-04-x-o  [C0402_2]  166.65 227.13 180 bottom
SC8  .1u-16vx7-04-x-o  [C0402_2]  173.84 227.13 0 bottom
SC9  .1u-16vx7-04-x-o  [C0402_2]  183.64 226.54 0 bottom
SC10  .1u-16vy5-04-x-o  [C0402_2]  146.76 226.44 90 bottom
SC11  .1u-16vx7-04-x-o  [C0402_2]  183.64 225.48 0 bottom
SC12  .1u-16vx7-04-x-o  [C0402_2]  183.64 224.33 0 bottom
SC13  .1u-16vx7-04-x-o  [C0402_2]  183.64 223.19 0 bottom
SC14  .1u-16vx7-04-x-o  [C0402_2]  183.64 222.05 0 bottom
SC15  .1u-16vx7-04-x  [C0402_2]  62.03 211.35 0 bottom
SC16  47p-04-x-o  [C0402_2]  151.1 179.1 90 bottom
SC17  10p-04-x-o  [C0402_2]  147.68 174.75 270 bottom
SC18  10p-04-x-o  [C0402_2]  148.82 174.75 270 bottom
SC19  10p-04-x-o  [C0402_2]  149.96 174.75 270 bottom
SC20  22u-6v3x5-x  [C0603_4D7UF]  113.26 154.89 0 bottom
SC21  22u-6v3x5-x  [C0603_4D7UF]  113.26 153.42 180 bottom
SC23  47u-6v3x5-08-x-o  [C0805_2]  131.42 153.03 180 bottom
SC24  47u-6v3x5-08-x-o  [C0805_2]  131.42 151.13 180 bottom
SC25  22u-6v3x5-x  [C0603_4D7UF]  115.87 150.8 180 bottom
SC26  22u-6v3x5-x  [C0603_4D7UF]  115.87 149.33 180 bottom
SC27  22u-6v3x5-08-x  [C0805_2]  131.42 149.23 180 bottom
SC28  22u-6v3x5-x  [C0603_4D7UF]  111.23 149.17 0 bottom
SC29  22u-6v3x5-x  [C0603_4D7UF]  115.87 147.85 180 bottom
SC30  330u-2vt-o  [C7343_1]  122.53 147.7 180 bottom
SC31  22u-6v3x5-08-x  [C0805_2]  131.42 147.32 180 bottom
SC32  22u-6v3x5-08-x  [C0805_2]  131.42 145.42 180 bottom
SC33  22u-6v3x5-08-x  [C0805_2]  131.42 143.51 180 bottom
SC34  22u-6v3x5-08-x  [C0805_2]  135.03 141.63 270 bottom
SC36  22u-6v3x5-x  [C0603_4D7UF]  114.43 139.83 180 bottom
SC37  10p-04-x-o  [C0402_2]  29.31 124.21 270 bottom
SC38  10p-04-x-o  [C0402_2]  30.71 124.21 270 bottom
SC39  22u-6v3x5-x-o  [C0603_4D7UF]  27.89 123.93 90 bottom
SC40  22u-6v3x5-x-o  [C0603_4D7UF]  45 122.68 90 bottom
SC41  10p-04-x-o  [C0402_2]  31.65 120.57 180 bottom
SC42  15p-04-x  [C0402_2]  37.54 63.93 180 bottom
SC43  15p-04-x  [C0402_2]  37.54 65.02 180 bottom
SC44  1u-6v3x5-04-x  [C0402_2]  60.96 58.27 0 bottom
SC45  47u-6v3x5-08-x  [C0805_2]  65.3 57.1 0 bottom
SC46  1u-6v3x5-04-x  [C0402_2]  56.92 55.02 90 bottom
SC47  1u-6v3x5-04-x  [C0402_2]  65.13 54.23 0 bottom
SC48  1u-6v3x5-04-x  [C0402_2]  49.33 53.47 270 bottom
SC49  1u-6v3x5-04-x  [C0402_2]  65.2 52.71 0 bottom
SC50  47u-6v3x5-08-x  [C0805_2]  59.92 52.22 180 bottom
SC51  22u-6v3x5-08-x  [C0805_2]  64.57 51.21 180 bottom
SC52  .1u-16vx7-04-x  [C0402_2]  72.21 48.44 90 bottom
SC53  1u-6v3x5-04-x  [C0402_2]  27.86 43.46 270 bottom
SC54  22u-6v3x5-08-x  [C0805_2]  26.31 42.88 270 bottom
SC55  1u-6v3x5-04-x  [C0402_2]  70.51 35.46 90 bottom
SC56  .1u-16vx7-04-x  [C0402_2]  58.47 33.91 180 bottom
SC57  10p-04-x-o  [C0402_2]  55.42 31.37 270 bottom
SC58  .1u-16vx7-04-x  [C0402_2]  65.76 30.35 270 bottom
SC59  1u-16vx7-06-x  [C0603_2]  59.72 25.35 0 bottom
SC60  .1u-25vx5-04-x  [C0402_2]  110.08 23.37 0 bottom
SC61  .01u-25vx7-04-x  [C0402_2]  110.08 22.22 0 bottom
SC62  10p-04-x-o  [C0402_2]  106.78 21.46 180 bottom
SC63  10u-6v3x5-06-x  [C0603_4D7UF]  110.46 20.96 0 bottom
SC64  10p-04-x-o  [C0402_2]  106.78 16.13 180 bottom
SC65  .01u-25vx7-04-x  [C0402_2]  92.05 15.62 90 bottom
SC66  .01u-25vx7-04-x  [C0402_2]  93.19 15.62 90 bottom
SC67  .1u-16vx7-04-x-o  [C0402_2]  89.84 14.55 90 bottom
SC68  .1u-16vx7-04-x-o  [C0402_2]  90.96 14.55 90 bottom
SC69  10u-6v3x5-06-x  [C0603_4D7UF]  110.34 9.02 0 bottom
SC70  .1u-25vx5-04-x  [C0402_2]  109.96 7.75 0 bottom
SC71  .01u-25vx7-04-x  [C0402_2]  109.96 6.65 0 bottom
SC645  1u-6v3x5-04-x-o  [C0402_2]  133.32 9.4 180 bottom
SP1  short pad  [SHORT2-NMNP]  125.83 190.63 270 top
SP2  short pad  [SHORT2-NMNP]  143.36 190.63 270 top
SP3  short pad  [SHORT2-NMNP]  125.83 188.85 90 top
SP4  short pad  [SHORT2-NMNP]  143.36 188.85 90 top
SP5  short pad  [SHORT2-NMNP]  177.9 169.8 0 top
SP6  short pad  [SHORT2-NMNP]  179.68 169.8 180 top
SP7  short pad  [SHORT2-NMNP]  177.9 151.76 0 top
SP8  short pad  [SHORT2-NMNP]  179.68 151.76 180 top
SP9  short pad  [SHORT2-NMNP]  177.9 134.37 0 top
SP10  short pad  [SHORT2-NMNP]  179.68 134.37 180 top
SPI_DEBUG  h5x2-bk-p2e-p1.27-o  [J5X2_PT1D27MM_SMD_2P_1]  64.19 15.65 0 top
SPIROM1  spi-8p-bk-o  [SOP8_W210_PT50_SPI_1]  63.64 7.87 90 top
SQ42  mmbt3904-s-x-o  [SOT23_BCE_2]  130.4 8.25 180 bottom
SQ43  mmbt3904-s-x-o  [SOT23_BCE_2]  130.4 12.19 180 bottom
SR1  2.2k-04-x-o  [R0402_2]  170.84 233.12 270 bottom
SR2  0-04-o  [R0402_2]  187.25 232.87 90 bottom
SR3  22-04-x-o  [R0402_2]  172.42 232.49 180 bottom
SR4  22-04-x-o  [R0402_2]  172.42 231.37 180 bottom
SR5  2.2k-04-x-o  [R0402_2]  170.84 231.04 90 bottom
SR6  100-04-x  [R0402_2]  147.68 179.1 270 bottom
SR7  56.2-1-04-x  [R0402_2]  148.82 179.1 270 bottom
SR8  56.2-1-04-x-o  [R0402_2]  149.96 179.1 270 bottom
SR9  1k-04-x  [R0402_2]  152.25 179.1 270 bottom
SR10  0-04-x  [R0402_2]  147.68 176.94 270 bottom
SR11  220-04-x  [R0402_2]  148.82 176.94 270 bottom
SR12  0-04-x  [R0402_2]  149.96 176.94 270 bottom
SR13  499-1-04-x  [R0402_2]  151.1 176.94 270 bottom
SR14  49.9-1-04-x-o  [R0402_2]  152.65 174.29 0 bottom
SR15  0-04-x  [R0402_2]  29.31 127.13 270 bottom
SR16  0-04-x  [R0402_2]  30.71 127.13 270 bottom
SR17  1m-04-x  [R0402_2]  39.17 64.54 270 bottom
SR19  0-x  [R0603_2]  61.8 49.2 270 bottom
SR20  33-04-x  [R0402_2]  50.52 43.23 0 bottom
SR21  0-04-x-o  [R0402_2]  50.52 42.09 0 bottom
SR22  0-04-x-o  [R0402_2]  34.14 41.15 180 bottom
SR23  33-04-x  [R0402_2]  50.55 41.02 0 bottom
SR24  33-04-x  [R0402_2]  50.55 39.88 0 bottom
SR25  33-04-x  [R0402_2]  50.55 38.74 0 bottom
SR26  4.7k-04-x-o  [R0402_2]  65.51 37.59 0 bottom
SR27  4.7k-04-x-o  [R0402_2]  67.92 37.59 180 bottom
SR28  1k-04-x  [R0402_2]  65.51 36.45 0 bottom
SR29  20k-04-x-o  [R0402_2]  67.92 36.45 180 bottom
SR30  15-04-x  [R0402_2]  65.51 35.31 0 bottom
SR31  15-04-x-o  [R0402_2]  67.92 35.31 180 bottom
SR32  0-04-x  [R0402_2]  106.78 18.41 180 bottom
SR33  0-04-x  [R0402_2]  106.78 17.27 0 bottom
SR34  10k-04-x  [R0402_2]  105.13 16.76 270 bottom
SR35  33-04-x  [R0402_2]  106.78 14.99 0 bottom
SR36  0-04-x  [R0402_2]  44.5 64.47 0 bottom
SR765  5.6k-1-04-x-o  [R0402_2]  133.32 10.54 0 bottom
SR766  1.13k-1-04-x-o  [R0402_2]  133.32 8.25 180 bottom
SR767  0-04-x-o  [R0402_2]  133.32 7.11 180 bottom
SR768  4.7k-04-x-o  [R0402_2]  132.94 12.19 90 bottom
STP1  tp  [TP30_SMD]  189.23 234.95 90 bottom
STP2  tp  [TP30_SMD]  194.03 234.19 0 bottom
STP3  tp  [TP30_SMD]  81.1 188.67 180 bottom
STP4  tp  [TP30_SMD]  80.7 181.74 180 bottom
STP5  tp  [TP4X20NP-BOT]  105.38 131.04 315 top
STP6  tp  [TP30_SMD]  93.32 181.74 180 bottom
STP7  tp  [TP30_SMD]  82.07 180.62 180 bottom
STP8  tp  [TP30_SMD]  76.56 180.09 180 bottom
STP9  tp  [TP30_SMD]  77.77 178.84 180 bottom
STP10  tp  [TP4X20NP-BOT]  103.86 130.68 0 top
STP11  tp  [TP4X20NP-BOT]  119.94 130.45 0 top
STP12  tp  [TP30_SMD]  72.44 176.73 180 bottom
STP13  tp  [TP30_SMD]  74.17 176.73 180 bottom
STP14  tp  [TP30_SMD]  113.28 169.52 180 bottom
STP15  tp  [TP30_SMD]  114.22 167.46 180 bottom
STP16  tp  [TP30_SMD]  112.45 166.4 180 bottom
STP17  tp  [TP30_SMD]  140.59 165.46 180 bottom
STP18  tp  [TP4X20NP-BOT]  55.58 55.45 90 top
STP19  tp  [TP4X20NP-BOT]  58.95 54.81 0 top
STP20  tp  [TP4X20NP-BOT]  58.08 53.07 135 top
STP21  tp  [TP4X20NP-BOT]  58.62 50.01 270 top
STP22  tp  [TP30_SMD]  116.33 165.33 180 bottom
STP23  tp  [TP4X20NP-BOT]  58.72 48.49 45 top
STP24  tp  [TP30_SMD]  113.46 163.4 180 bottom
STP25  tp  [TP4X20NP-BOT]  57.43 47.9 225 top
STP26  tp  [TP30_SMD]  141.94 162.46 180 bottom
STP27  tp  [TP30_SMD]  111.4 161.87 180 bottom
STP28  tp  [TP30_SMD]  115.82 159.99 180 bottom
STP29  tp  [TP30_SMD]  111.25 159.87 180 bottom
STP30  tp  [TP30_SMD]  115.9 158.72 180 bottom
STP31  tp  [TP30_SMD]  111.25 158.7 180 bottom
STP32  tp  [TP30_SMD]  113.92 158.55 180 bottom
STP33  tp  [TP30_SMD]  121.79 158.29 180 bottom
STP34  tp  [TP30_SMD]  117.58 158.17 180 bottom
STP35  tp  [TP30_SMD]  113.92 157.45 180 bottom
STP36  tp  [TP30_SMD]  111.4 156.36 180 bottom
STP37  tp  [TP30_SMD]  139.98 145.95 180 bottom
STP38  tp  [TP30_SMD]  141.4 145.92 180 bottom
STP39  tp  [TP30_SMD]  124.49 138.94 180 bottom
STP40  tp  [TP30_SMD]  77.04 64.85 0 bottom
STP41  tp  [TP30_SMD]  83.52 64.39 90 bottom
STP42  tp  [TP30_SMD]  75.29 63.8 0 bottom
STP43  tp  [TP30_SMD]  78.38 59.66 180 bottom
STP44  tp  [TP30_SMD]  76.56 59.64 0 bottom
STP45  tp  [TP30_SMD]  68.53 58.22 270 bottom
STP46  tp  [TP30_SMD]  72.97 56.67 0 bottom
STP47  tp  [TP30_SMD]  76.4 56.39 90 bottom
STP48  tp  [TP30_SMD]  77.95 55.12 270 bottom
STP49  tp  [TP30_SMD]  72.24 54.74 90 bottom
STP50  tp  [TP30_SMD]  74.02 54.61 90 bottom
STP51  tp  [TP30_SMD]  78.59 50.55 270 bottom
STP52  tp  [TP30_SMD]  59.56 50.04 270 bottom
STP53  tp  [TP30_SMD]  69.39 50.01 270 bottom
STP54  tp  [TP30_SMD]  78.59 48.77 270 bottom
STP55  tp  [TP30_SMD]  76.81 48.51 270 bottom
STP56  tp  [TP30_SMD]  63.04 48.13 270 bottom
STP57  tp  [TP30_SMD]  60.35 48.06 270 bottom
STP58  tp  [TP30_SMD]  76.81 46.74 270 bottom
STP59  tp  [TP30_SMD]  78.59 46.74 270 bottom
STP60  tp  [TP30_SMD]  80.37 46.74 270 bottom
STP61  tp  [TP30_SMD]  61.54 46.46 270 bottom
STP62  tp  [TP30_SMD]  76.81 44.96 270 bottom
STP63  tp  [TP30_SMD]  78.59 44.96 270 bottom
STP64  tp  [TP30_SMD]  80.37 44.96 270 bottom
STP65  tp  [TP30_SMD]  47.14 43.59 180 bottom
STP66  tp  [TP30_SMD]  76.81 43.18 90 bottom
STP67  tp  [TP30_SMD]  80.37 43.18 180 bottom
STP68  tp  [TP30_SMD]  78.54 43.13 0 bottom
STP69  tp  [TP30_SMD]  46.76 41.83 90 bottom
STP70  tp  [TP30_SMD]  66.17 41.38 270 bottom
STP71  tp  [TP30_SMD]  48.34 41.05 180 bottom
STP72  tp  [TP30_SMD]  62.33 39.12 0 bottom
STP73  tp  [TP30_SMD]  73.74 37.95 0 bottom
STP74  tp  [TP30_SMD]  52.27 30.91 0 bottom
SY1  x-24m-smd-x  [CRYSTAL_4P_PT2D2X1D6_SMD]  34.32 65.13 90 bottom
SYS_FAN  h4x1-pow  [J4X1_WAFER]  185.01 51.56 90 top
TP3  tp  [TP30_SMD]  193.83 226.03 270 top
TP5  testing point  [TP30_SMD]  23.22 208.86 0 top
TP8  tp  [TP30_SMD]  91.31 60.91 270 top
TP9  tp  [TP30_SMD]  40.87 59.94 0 top
TP10  tp  [TP30_SMD]  39.34 60.22 0 top
TP11  tp  [TP30_SMD]  81.25 48.01 90 top
TP12  tp  [TP30_SMD]  82.35 46.61 90 top
TP13  tp  [TP30_SMD]  81.25 44.96 270 top
TP14  tp  [TP30_SMD]  81.25 43.18 270 top
